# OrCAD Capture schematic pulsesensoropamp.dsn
size A
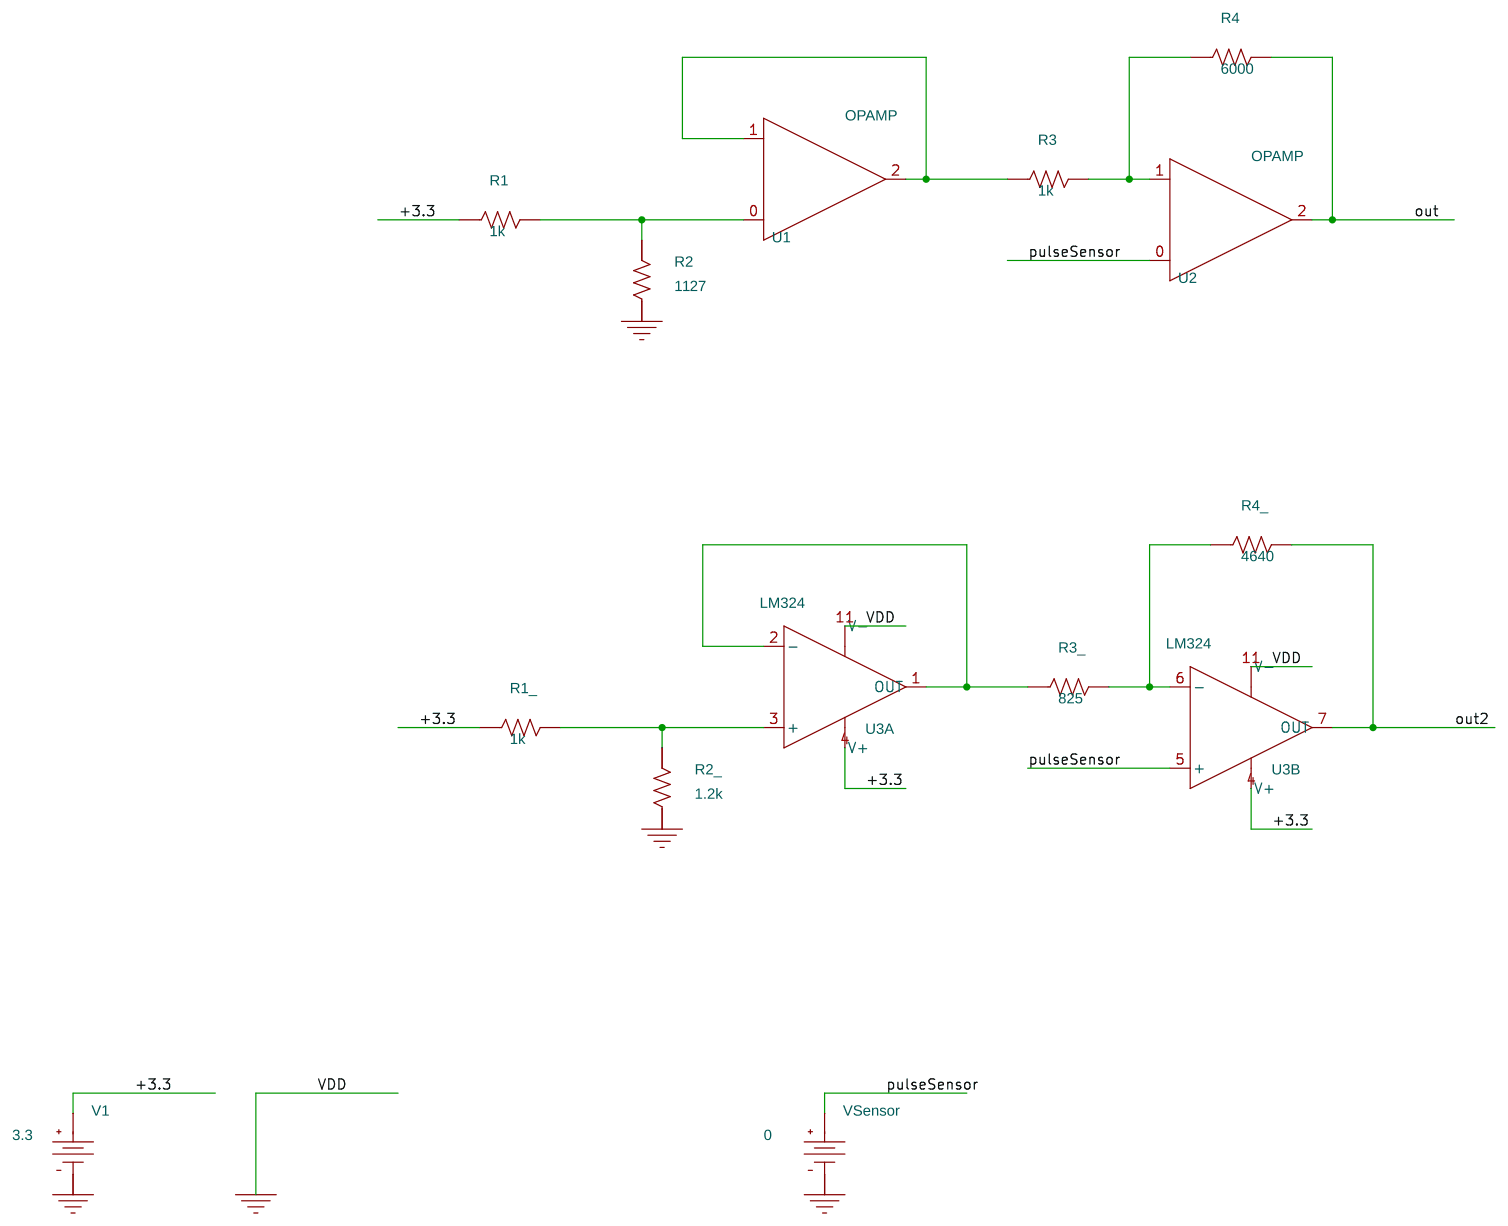
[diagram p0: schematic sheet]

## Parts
R1  1k  [AXRC05]
R1_  1k  [AXRC05]
R2  1127  [AXRC05]
R2_  1.2k  [AXRC05]
R3  1k  [AXRC05]
R3_  825  [AXRC05]
R4  6000  [AXRC05]
R4_  4640  [AXRC05]
U1  OPAMP
U2  OPAMP
U3  LM324  [DIP10014W300L800]  (sections A,B)
V1  VDC
VSensor  VDC

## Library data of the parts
R1 R1_ R2 R2_ R3 R3_ R4 R4_ = R
U1 U2 = OPAMP: VNEG: 0; VPOS: 20
U3 = LM324
V1 = VDC: DC: 3.3
VSensor = VDC: DC: 0

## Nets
0: R2.1 R2_.1 U3.11(V-) V1.1(-) VSensor.1(-)
+3.3: R1.1 R1_.1 U3.4(V+) V1.0(+)
out: R4.2 U2.2(OUT)
out2: R4_.2 U3.7(OUT)
pulseSensor: U2.0(+) U3.5(+) VSensor.0(+)
N15102: R3.1 U1.1(-) U1.2(OUT)
N15106: R3.2 R4.1 U2.1(-)
N15238: R1.2 R2.2 U1.0(+)
N15736: R3_.1 U3.1(OUT) U3.2(-)
N15764: R3_.2 R4_.1 U3.6(-)
N15884: R1_.2 R2_.2 U3.3(+)
